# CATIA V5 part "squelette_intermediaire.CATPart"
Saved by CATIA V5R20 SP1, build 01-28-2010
Part number: squelette_intermediaire
Bounding box of the stored display mesh (mm): x -5 to 5, y 500 to 500, z 0 to 0
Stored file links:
  C:\Users\Fox\Desktop\IAO Projet\A RENDRE\Sauvegarde IFMA\squelette_intermediaire.CATPart
  C:\Users\Fox\Desktop\IAO Projet\A RENDRE\Sauvegarde IFMA\squelette.CATProduct
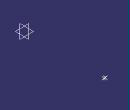
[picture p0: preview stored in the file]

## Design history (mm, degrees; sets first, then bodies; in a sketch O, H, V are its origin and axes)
Set1
  Line1: type PtPt, FirstPoint Point1, SecondPoint Point2
  Line2: type PtPt, FirstPoint Point2, SecondPoint Point3
Set2
  Point1 to Point3: linked copy from another document
Body1 (main body)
